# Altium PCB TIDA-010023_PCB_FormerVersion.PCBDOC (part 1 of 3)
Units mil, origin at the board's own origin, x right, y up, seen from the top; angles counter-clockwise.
Board outline 4724.44 x 3937.01 mil, 2 copper layers (Top Layer, Bottom Layer), stack 62 mil thick; 263 components, 126 nets, 611 pads, 186 vias.
Unrouted connection lines stored in the file: 58.
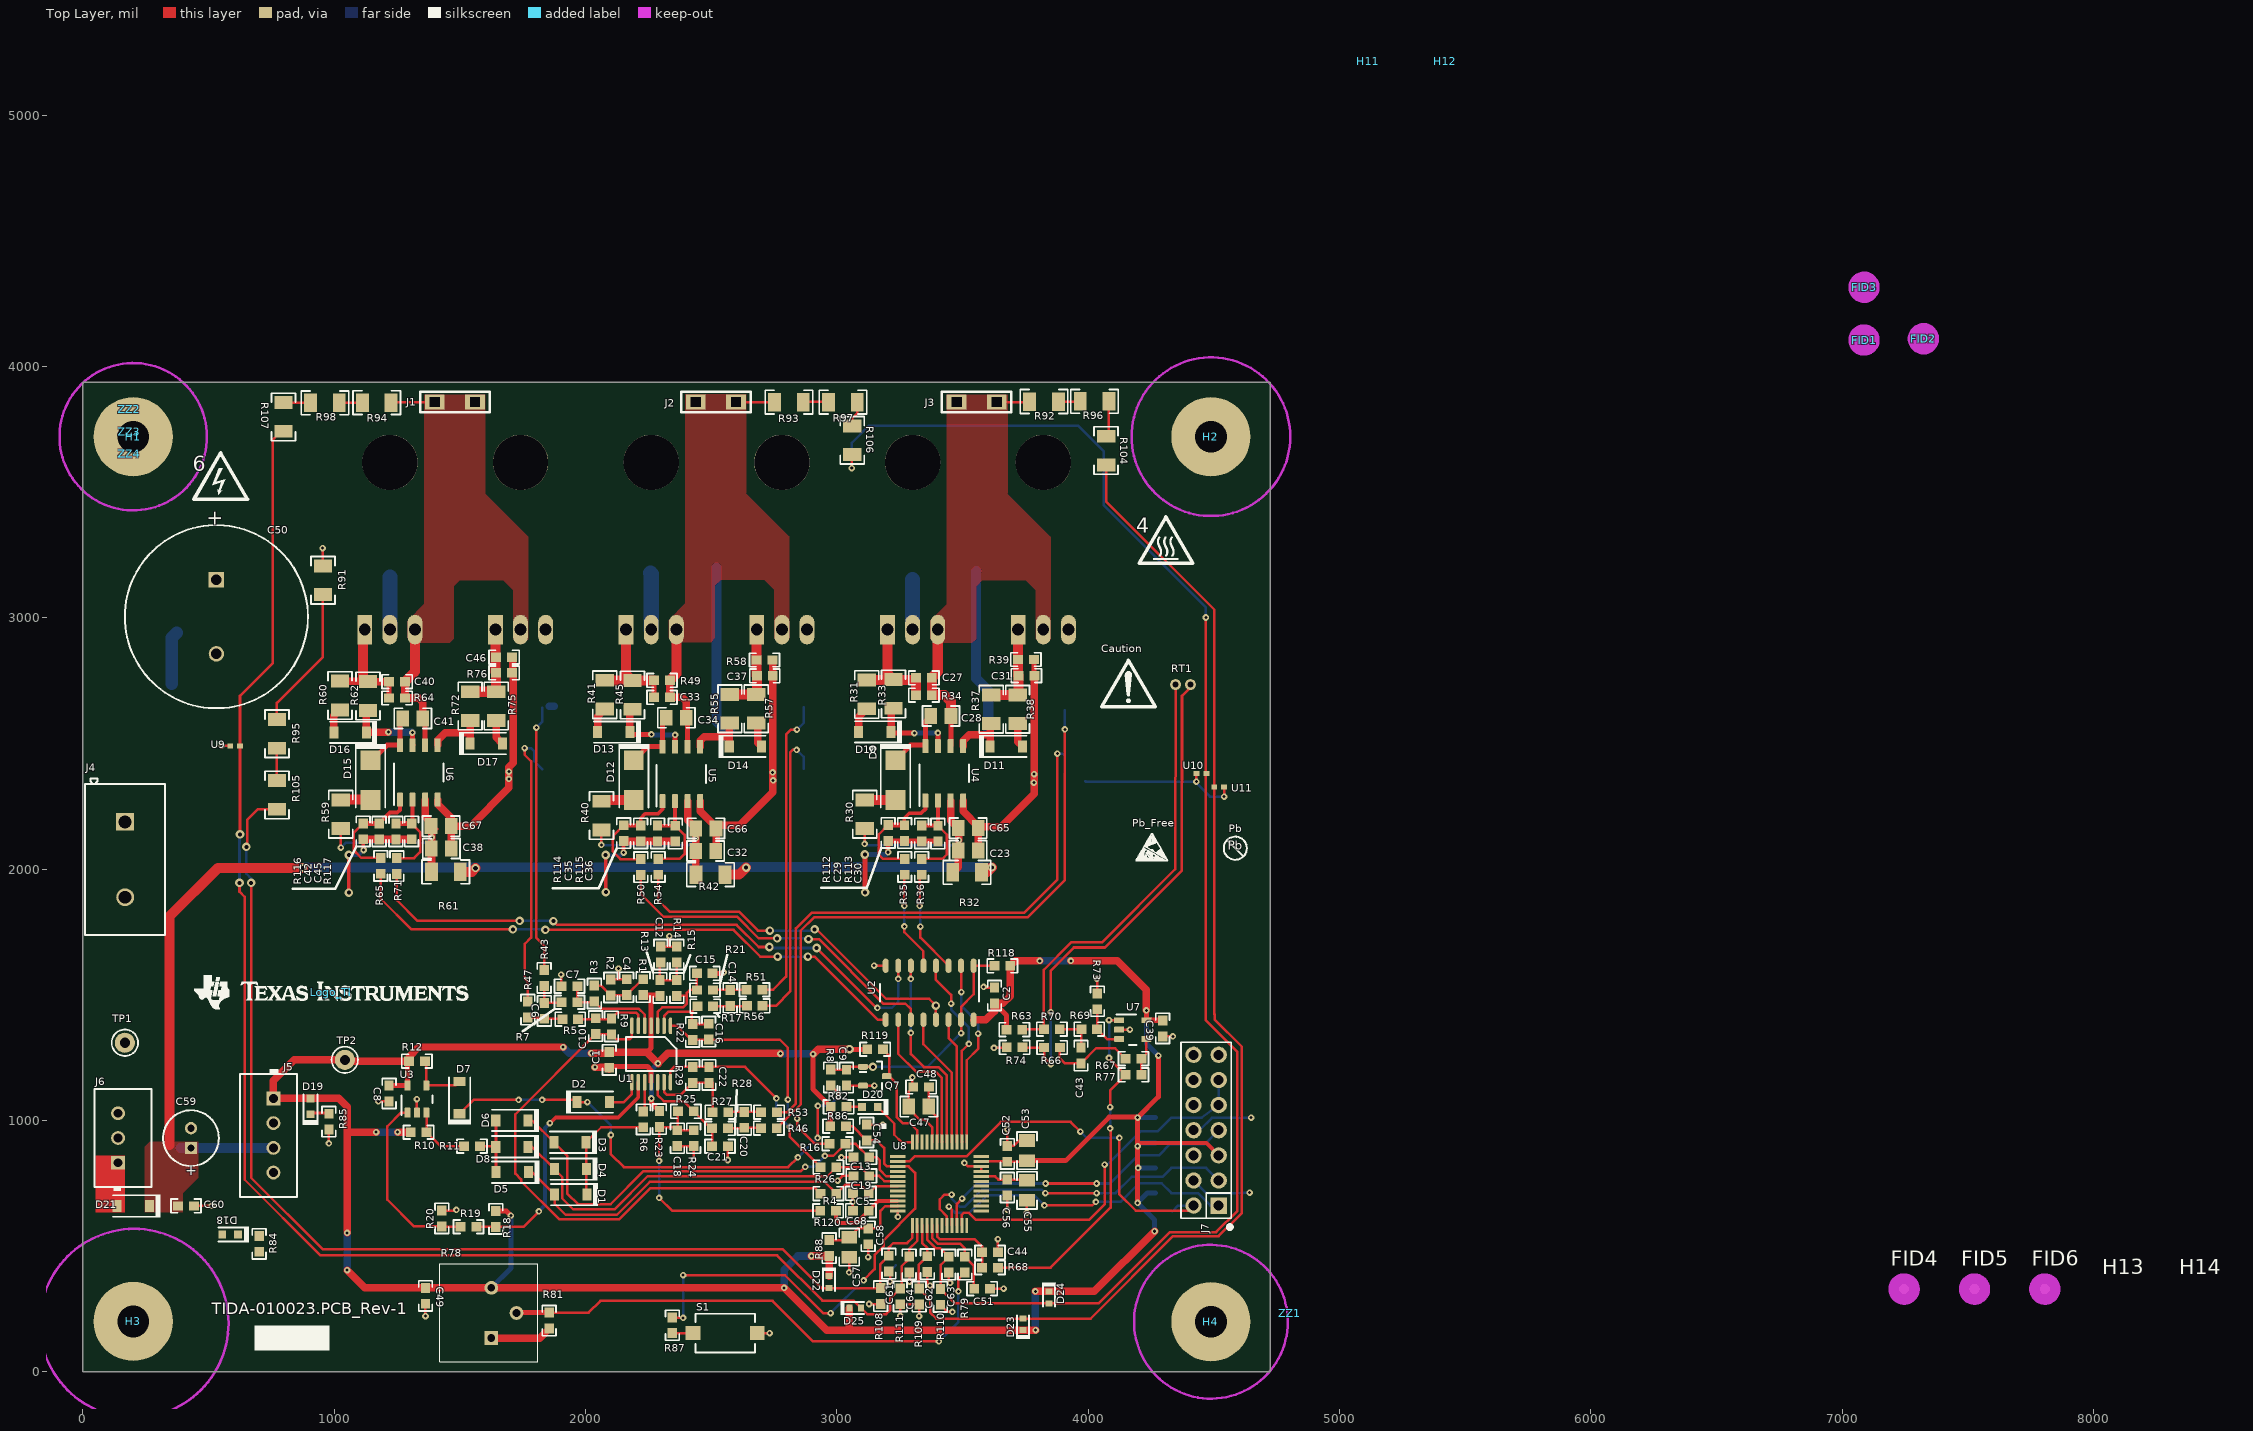
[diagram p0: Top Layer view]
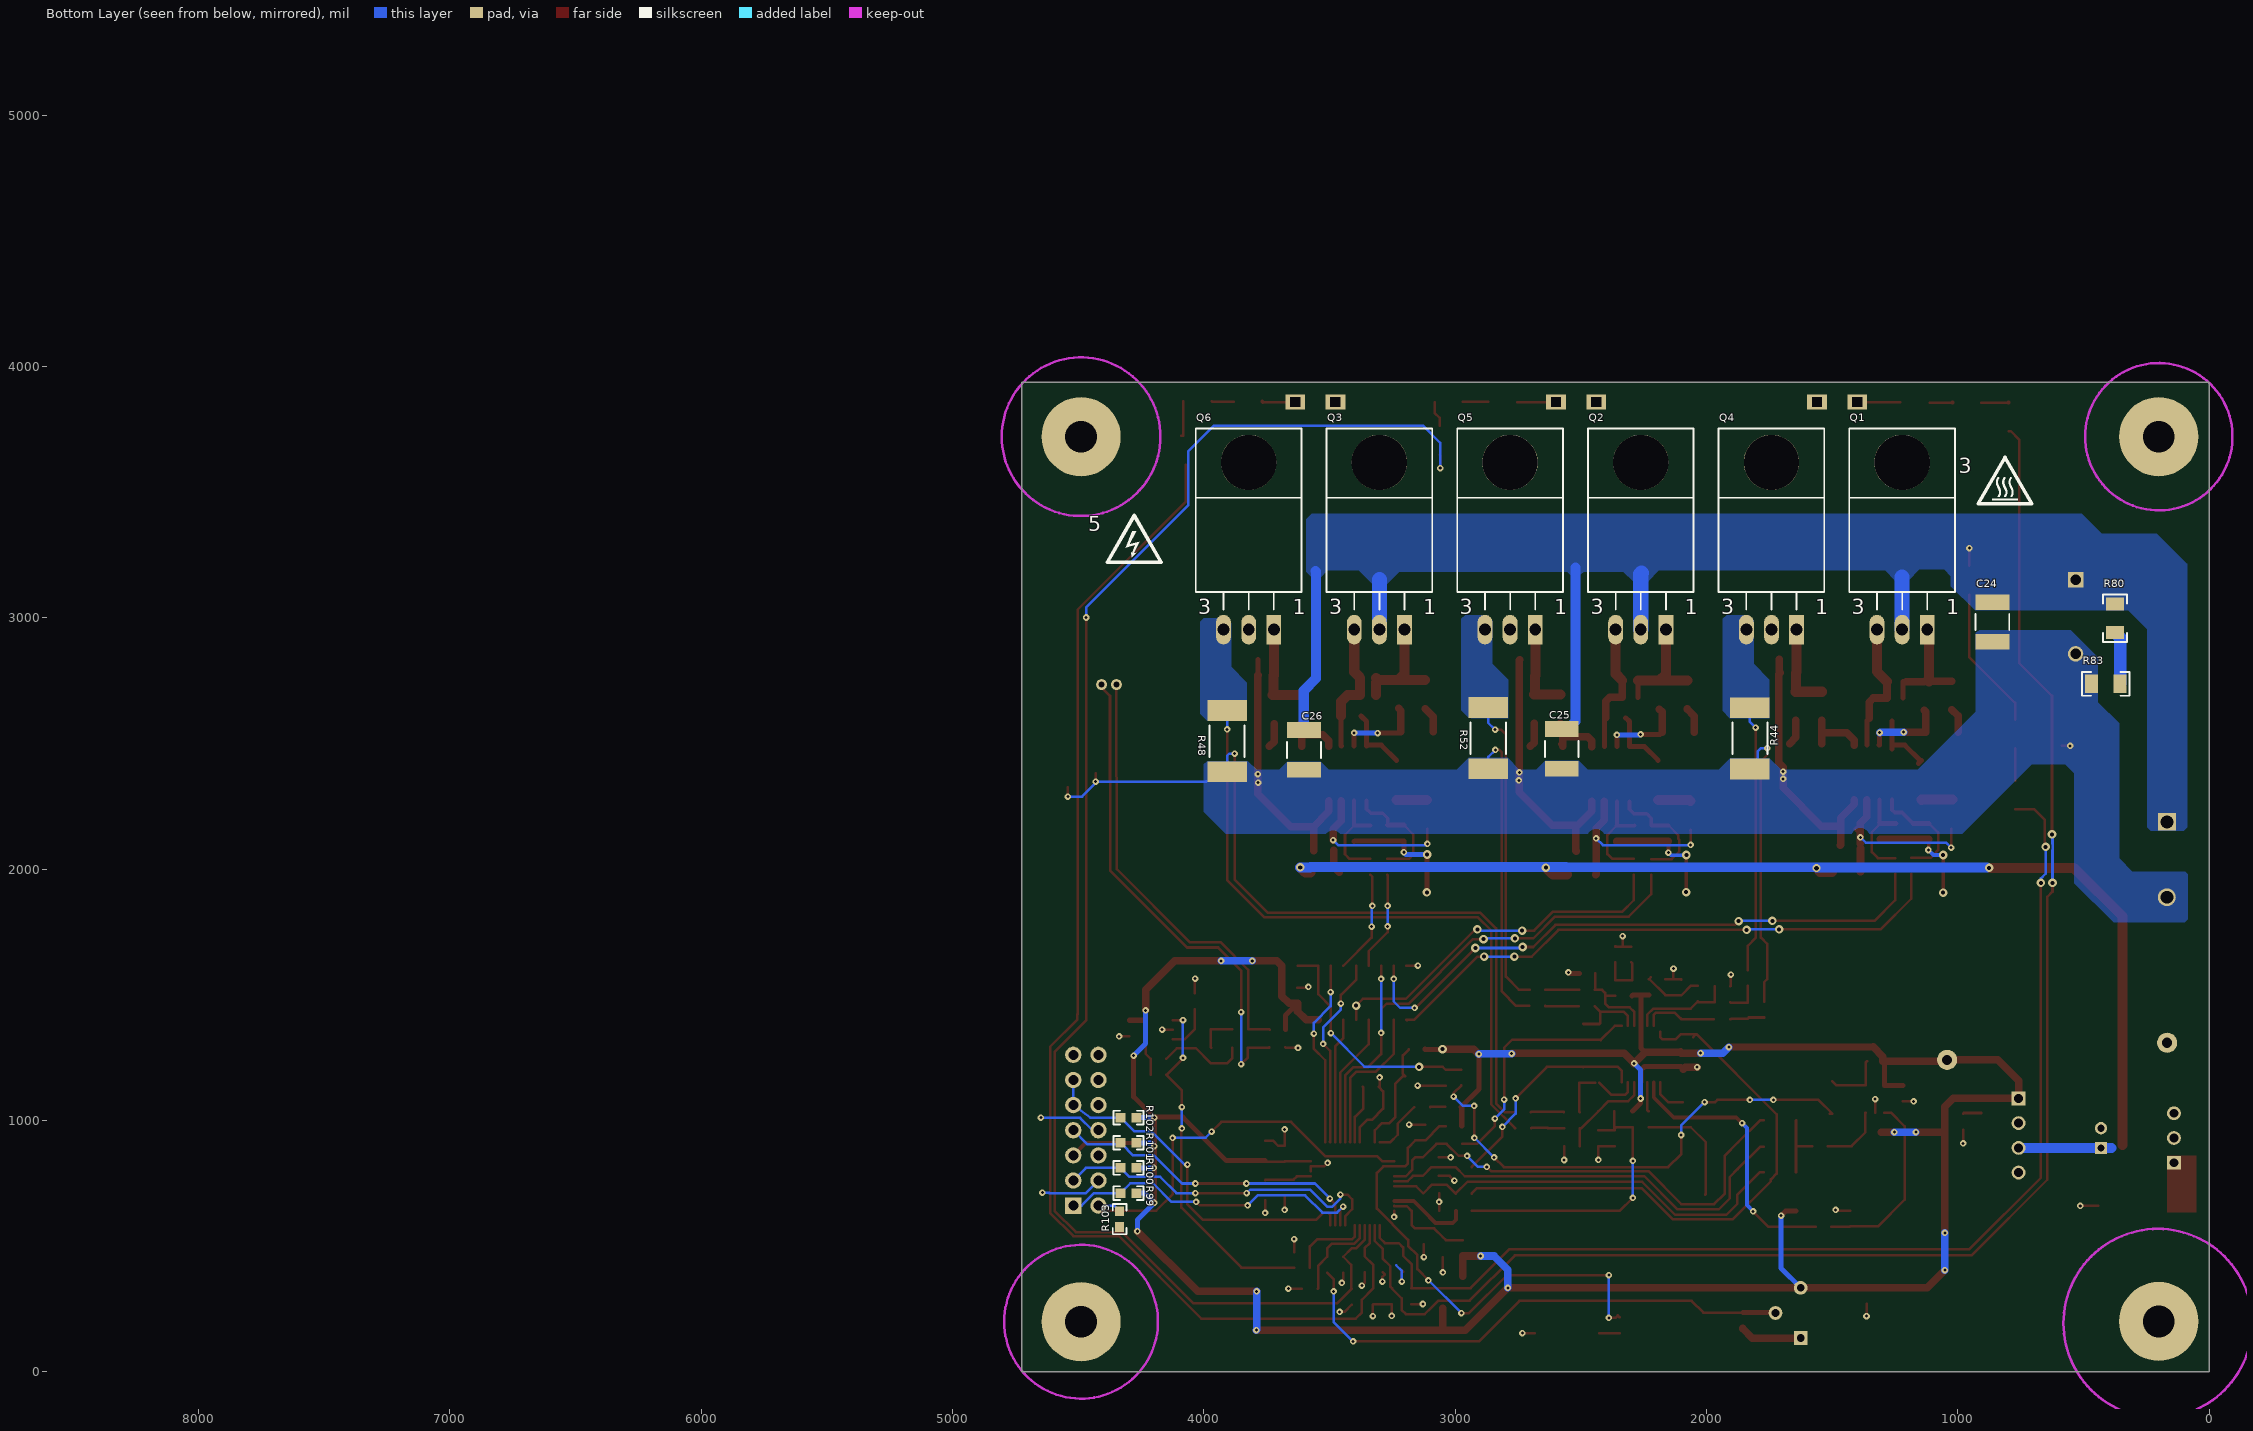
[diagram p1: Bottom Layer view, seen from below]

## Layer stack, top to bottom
Top Solder: solder mask 0.4, Solder Resist, Dk 3.5
Top Layer: signal copper 1.4
Dielectric1: core 59.2, FR-4, Dk 4.8
Bottom Layer: signal copper 1.4
Bottom Solder: solder mask 0.4, Solder Resist, Dk 3.5

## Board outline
0,0 0,3937.01 4723.44,3937.01 4724.44,0

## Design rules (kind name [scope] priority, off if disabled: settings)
AcuteAngle [All] p1: minimum=4.50000000000000E+0001 checktracksonly=FALSE
AssemblyTestPointUsage [All] p1: valid=2
BoardOutlineClearance BoardOutlineClearance_MountingHoles [OnCopper and InComponentClass('Mounting Holes')] p1: gap=40 ignorepadtopadclearanceinfootprint=FALSE
BoardOutlineClearance BoardOutlineClearance_Poly [OnCopper and IsPoly] p2: gap=25 ignorepadtopadclearanceinfootprint=FALSE
BoardOutlineClearance [OnCopper and Not InComponentClass('Logo') and not InComponentClass('FiducialMark') and not InRegion(1000,500,4000,800) and not InPoly] p3 off: gap=75 ignorepadtopadclearanceinfootprint=FALSE
Clearance Clearance_Keepouts [((IsTrack Or IsArc) And Not InPoly) And IsFree and IsKeepOut vs ((IsTrack Or IsArc) And Not InPoly) And IsFree and IsKeepOut] p1: gap=0 ignorepadtopadclearanceinfootprint=FALSE
Clearance Clearance_Poly [InPolygon] p2: gap=25 ignorepadtopadclearanceinfootprint=FALSE except(0: Arc-Hole Track-Hole SMDPad-Hole THPad-Hole Via-Hole Fill-Hole Poly-Hole Region-Hole Text-Hole)
Clearance Clearance_FiducialMark [IsKeepOut and InComponentClass('FiducialMark') vs IsPad and InComponentClass('FiducialMark')] p3: gap=0 ignorepadtopadclearanceinfootprint=FALSE
Clearance [All] p4: gap=6 ignorepadtopadclearanceinfootprint=FALSE
ComponentClearance ComponentClearance_MountingHoles_FiducialMarks [InComponentClass('Mounting Holes') vs InComponentClass('FiducialMark')] p1: gap=50 collisioncheckmode=3 verticalgap=10 showdistances=FALSE
ComponentClearance ComponentClearance_Shunt [InComponentClass('Header') vs InComponentClass('Shunt')] p2: gap=0 collisioncheckmode=3 verticalgap=0 showdistances=FALSE
ComponentClearance ComponentClearance_Logo [InComponentClass('Logo')] p3: gap=50 collisioncheckmode=3 verticalgap=10 showdistances=FALSE
ComponentClearance ComponentClearance_ScrewToNut [(HasFootprint('NY PMS 440 0025 PH')) vs (HasFootprint('Keystone_1902C'))] p4: gap=5 collisioncheckmode=3 verticalgap=5 showdistances=FALSE
ComponentClearance ComponentClearance_MountingHoles [InComponentClass('Mounting Holes')] p5: gap=-100 collisioncheckmode=3 verticalgap=0 showdistances=TRUE
ComponentClearance ComponentClearance_SmallPassives [HasFootprint('0201*') or HasFootprint('0402*') or HasFootprint('0508') or HasFootprint('0603*') or HasFootprint('0612') or HasFootprint('0805*') or HasFootprint('0815*') or HasFootprint('0830*') or HasFootprint('1206*') or HasFootprint('1210*') or HasFootprint('1808*') or HasFootprint('1812*') or HasFootprint('1825*') or HasFootprint('2010*') or HasFootprint('2220*') or HasFootprint('2225*') or HasFootprint('2512*') or HasFootprint('2728*') or HasFootprint('3518*') vs HasFootprint('0201*') or HasFootprint('0402*') or HasFootprint('0508') or HasFootprint('0603*') or HasFootprint('0612') or HasFootprint('0805*') or HasFootprint('0815*') or HasFootprint('0830*') or HasFootprint('1206*') or HasFootprint('1210*') or HasFootprint('1808*') or HasFootprint('1812*') or HasFootprint('1825*') or HasFootprint('2010*') or HasFootprint('2220*') or HasFootprint('2225*') or HasFootprint('2512*') or HasFootprint('2728*') or HasFootprint('3518*')] p6: gap=14.96 collisioncheckmode=3 verticalgap=10 showdistances=FALSE
ComponentClearance ComponentClearance_THtoSMT [IsThruComponent vs IsSMTComponent] p7: gap=0 collisioncheckmode=3 verticalgap=0 showdistances=FALSE
ComponentClearance ComponentClearance_THtoTH [IsThruComponent vs IsThruComponent] p8: gap=15 collisioncheckmode=3 verticalgap=30 showdistances=FALSE
ComponentClearance [All] p9: gap=30 collisioncheckmode=3 verticalgap=10 showdistances=FALSE
DiffPairsRouting [All] p1: maxlimit=100 minlimit=10 mostfreqgap=10 toplayer_minwidth=15 toplayer_maxwidth=15 toplayer_prefwidth=15 bottomlayer_minwidth=15 bottomlayer_maxwidth=15 bottomlayer_prefwidth=15 maxuncoupledlength=1000
FabricationTestPointUsage TestPointUsage [All] p1: valid=2 allowmultiple=FALSE
FabricationTestpoint Testpoint [All] p1: side=3 testpointundercomponent=TRUE minsize=40 maxsize=100 preferedsize=60 minholesize=0 maxholesize=40 preferedholesize=32 testpointgrid=1 allowsidetop=TRUE allowsidebottom=TRUE usegrid=TRUE gridtolerance=0.01
FanoutControl Fanout_LCC [IsLCC] p1: bgadir=Out bgaviamode=Centered fanoutstyle=Auto fanoutdirection=Alternating viagrid=1 // Fanout_LCC (Default Rule)
FanoutControl Fanout_BGA [IsBGA] p2: bgadir=Out bgaviamode=Centered fanoutstyle=Auto fanoutdirection=Alternating viagrid=1 // Fanout_BGA (Default Rule)
FanoutControl Fanout_Default [All] p4: bgadir=Out bgaviamode=Centered fanoutstyle=Auto fanoutdirection=Alternating viagrid=1 // Fanout_Default (Default Rule)
FanoutControl Fanout_Small [(CompPinCount < 5)] p5: bgadir=Out bgaviamode=Centered fanoutstyle=Auto fanoutdirection=OutThenIn viagrid=1 // Fanout_Small (Default Rule)
Height [All] p1: minheight=0 maxheight=5000 prefheight=500
HoleSize [All] p1: absolutevalues=TRUE maxlimit=251 minlimit=7.87 maxpercent=80.000 minpercent=20.000
MinimumAnnularRing MinimumAnnularRing_ThermalPadVias [IsVia and InAnyComponent] p1: minimumring=5.91
MinimumAnnularRing [All] p2: minimumring=8
MinimumSolderMaskSliver MinimumSolderMaskSliver_Logo [InComponentClass('Logo') vs InComponentClass('Logo')] p1: minsoldermaskwidth=0.7
MinimumSolderMaskSliver [All] p2: minsoldermaskwidth=3.94
PlaneConnect [All] p1: planeconnectstyle=Relief reliefexpansion=10 reliefentries=4 reliefconductorwidth=10 reliefairgap=10
PolygonConnect [All] p1: connectstyle=Direct reliefconductorwidth=10 reliefentries=4 polygonreliefangle="90 Angle" airgapwidth=10
RoutingVias ThermalPadVias [IsVia and InAnyComponent] p1: holewidth=7.87 width=19.68 viastyle="Through Hole" minholewidth=7.87 minwidth=19.68 maxholewidth=12.99 maxwidth=23.62
RoutingVias [All] p2: holewidth=16 width=34 viastyle="Through Hole" minholewidth=7.87 minwidth=26 maxholewidth=40 maxwidth=65
SilkToBoardRegionClearance [Not ((IsComment or IsDesignator) And (Hide <> 'False')) and not InRegion(1000,500,4000,800)] p1:
SilkToSilkClearance SilkToSilkClearance_Pb-FreeLogo [(HasFootprint('Pb-Free_Overlay_Medium') OR HasFootprint('Pb-Free_Overlay_Small')) vs (HasFootprint('Pb-Free_Overlay_Medium') OR HasFootprint('Pb-Free_Overlay_Small'))] p1: silktosilkclearance=0
SilkToSilkClearance [All] p2: silktosilkclearance=0
SilkToSolderMaskClearance SilkToComponentPadClearance [(IsPad or IsFill or IsRegion) and InAnycomponent] p1: minsilkscreentomaskgap=0 clearancetoexposedcopper=TRUE
SilkToSolderMaskClearance "Silk to Solder Mask Opening" [All] p2: minsilkscreentomaskgap=0 clearancetoexposedcopper=FALSE
SolderMaskExpansion [All] p1: expansion=1.97
Width [All] p1: maxlimit=300 minlimit=6 preferedwidth=10 minimp=50.000000 maximp=50.000000 favimp=50.000000 checkconnectedcopper=TRUE
14 further rules are at their usual default settings.

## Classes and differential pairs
component class TIDA-010023_MCU: C47 C48 C49 C50 C51 C52 C53 C54 C55 C56 C57 C58 C59 C60 C61 C62 C63 C64 C68 D18 D19 D20 D21 D22 D23 D24 D25 J4 J5 J6 J7 R78 R79 R80 R81 R82 R83 R84 R85 R86 R87 R88 R91 R92 R93 R94 R95 R96 R97 R98 R99 R100 R101 R102 R103 R104 R105 R106 R107 R108 R109 R110 R111 R120 S1 TP1 TP2 U8 U9 U10 U11
component class TIDA-010023_Inverter: C23 C24 C25 C26 C27 C28 C29 C30 C31 C32 C33 C34 C35 C36 C37 C38 C39 C40 C41 C42 C43 C44 C45 C46 C65 C66 C67 D9 D10 D11 D12 D13 D14 D15 D16 D17 J1 J2 J3 Q1 Q2 Q3 Q4 Q5 Q6 R30 R31 R32 R33 R34 R35 R36 R37 R38 R39 R40 R41 R42 R43 R44 R45 R46 R47 R48 R49 R50 R51 R52 R53 R54 R55 R56 R57 R58 R59 R60 R61 R62 R63 R64 R65 R66 R67 R68 R69 R70 R71 R72 R73 R74 R75 R76 R77 R112 R113 R114 R115 R116 R117 RT1 U4 U5 U6
component class TIDA-010023_Current_Sensing: C1 C2 C4 C5 C6 C7 C8 C9 C10 C12 C13 C14 C15 C16 C18 C19 C20 C21 C22 D1 D2 D3 D4 D5 D6 D7 D8 Q7 R1 R2 R3 R4 R5 R6 R7 R8 R9 R10 R11 R12 R13 R14 R15 R16 R17 R18 R19 R20 R21 R22 R23 R24 R25 R26 R27 R28 R29 R118 R119 U1 U2 U3
component class Header: J7
component class AssemblyNote: ZZ1 ZZ2 ZZ3 ZZ4
component class FiducialMark: FID1 FID2 FID3 FID4 FID5 FID6
component class TIDA-010023_EVM_Hardware: 3 4 5 6 Caution FID1 FID2 FID3 FID4 FID5 FID6 H1 H2 H3 H4 H11 H12 H13 H14 Logo_TI Pb Pb_Free ZZ1 ZZ2 ZZ3 ZZ4
component class "Mounting Holes": H1 H2 H3 H4
component class Logo: Logo_TI

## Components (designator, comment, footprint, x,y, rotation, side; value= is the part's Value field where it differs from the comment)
3 "CAUTION HOT SURFACE" IEC_HotSurface_small 812,3546 r180 bottom
4 "CAUTION HOT SURFACE" IEC_HotSurface_small 4309,3309 r0 top
5 "HIGH VOLTAGE" IEC_HighVoltage_small 4276.5,3309.5 r180 bottom
6 "HIGH VOLTAGE" IEC_HighVoltage_small 548,3559 r0 top
C1 "0603YC104JAT2A" 0603 2094,1241 r270 top value=0.1uF
C2 "0603YC104JAT2A" 0603 3627,1497 r270 top value=0.1uF
C4 "0603YC104JAT2A" 0603 2163,1530 r270 top value=0.1uF
C5 "06035A221FAT2A" 0603 3095,710 r180 top value=220pF
C6 "06035A221FAT2A" 0603 1836,1436 r90 top value=220pF
C7 "06035A221FAT2A" 0603 1936,1534 r180 top value=220pF
C8 "0603YC104JAT2A" 0603 1218,1107 r270 top value=0.1uF
C9 "06035A221FAT2A" 0603 3038,1170 r270 top value=220pF
C10 "06035A221FAT2A" 0603 2040,1375 r90 top value=22pF
C12 "0603YC104JAT2A" 0603 2299,1660 r90 top value=0.1uF
C13 "06035A221FAT2A" 0603 3097,853 r180 top value=220pF
C14 "06035A221FAT2A" 0603 2575,1487 r90 top value=220pF
C15 "06035A221FAT2A" 0603 2474,1585 r0 top value=220pF
C16 "06035A221FAT2A" 0603 2490,1353 r90 top value=22pF
C18 "0603YC104JAT2A" 0603 2364.98,929.2 r270 top value=0.1uF
C19 "06035A221FAT2A" 0603 3097,779 r180 top value=220pF
C20 "06035A221FAT2A" 0603 2631.98,1002.2 r90 top value=220pF
C21 "06035A221FAT2A" 0603 2534.98,897.2 r0 top value=220pF
C22 "06035A221FAT2A" 0603 2491,1181 r270 top value=22pF
C23 "C2012X5R1E106K125AB" 0805_HV 3522,2074 r180 top value=10uF
C24 "C1812V104KDRACTU" 1812_254 862,2983 r270 bottom value=0.1uF
C25 "C1812V104KDRACTU" 1812_254 2575,2478 r270 bottom value=0.1uF
C26 "C1812V104KDRACTU" 1812_254 3601,2474 r270 bottom value=0.1uF
C27 "GRM188R71E222KA01D" 0603 3346,2761 r0 top value=2200pF
C28 "C0805C105K3RACTU" 0805_HV 3414,2609 r0 top value=1uF
C29 "06035A221FAT2A" 0603 3269,2143 r270 top value=220pF
C30 "06035A221FAT2A" 0603 3402,2141 r270 top value=220pF
C31 "GRM188R71E222KA01D" 0603 3754,2770 r0 top value=2200pF
C32 "C2012X5R1E106K125AB" 0805_HV 2478,2072 r180 top value=10uF
C33 "GRM188R71E222KA01D" 0603 2304,2683 r0 top value=2200pF
C34 "C0805C105K3RACTU" 0805_HV 2361,2602 r0 top value=1uF
C35 "06035A221FAT2A" 0603 2219.3,2142 r270 top value=220pF
C36 "06035A221FAT2A" 0603 2357.3,2141 r270 top value=220pF
C37 "GRM188R71E222KA01D" 0603 2713,2769 r0 top value=2200pF
C38 "C2012X5R1E106K125AB" 0805_HV 1426,2082 r180 top value=10uF
C39 "0603YC104JAT2A" 0603 4296,1366 r270 top value=0.1uF
C40 "GRM188R71E222KA01D" 0603 1250,2745.7 r0 top value=2200pF
C41 "C0805C105K3RACTU" 0805_HV 1312.52,2599.6 r0 top value=1uF
C42 "06035A221FAT2A" 0603 1178.52,2149.6 r270 top value=220pF
C43 "0603YC104JAT2A" 0603 3971,1258 r270 top value=0.1uF
C44 "0603YC104JAT2A" 0603 3609,475 r180 top value=0.1uF
C45 "06035A221FAT2A" 0603 1245.52,2149.6 r270 top value=220pF
C46 "GRM188R71E222KA01D" 0603 1675.68,2843.5 r0 top value=2200pF
C47 "GRM21BR71C475KA73L" 0805_HV 3326,1055 r0 top value=4.7uF
C48 "0603YC104JAT2A" 0603 3335,1133 r0 top value=0.1uF
C49 "0603YC104JAT2A" 0603 1363,302 r90 top value=0.1uF
C50 "UCS2W680MHD" CS_1800x3150 531,3004 r270 top value=68uF
C51 "0603YC104JAT2A" 0603 3578,331 r180 top value=0.1uF
C52 "0603YC104JAT2A" 0603 3678,867 r90 top value=0.1uF
C53 "GRM21BR71C475KA73L" 0805_HV 3756,880 r90 top value=4.7uF
C54 "0603YC104JAT2A" 0603 3118,952 r90 top value=0.1uF
C55 "GRM21BR71C475KA73L" 0805_HV 3756,722 r270 top value=4.7uF
C56 "0603YC104JAT2A" 0603 3678,733 r270 top value=0.1uF
C57 "GRM21BR71C475KA73L" 0805_HV 3049,496 r270 top value=4.7uF
C58 "0603YC104JAT2A" 0603 3124,539 r270 top value=0.1uF
C59 "URZ1E220MDD1TD" RZ_500x900 430,929.61 r90 top value=22uF
C60 "06033C104KAT2A" 0603 410,659.61 r0 top value=0.1uF
C61 "06033C473JAT2A" 0603 3207,430 r270 top value=0.047uF
C62 "06033C473JAT2A" 0603 3360,428 r270 top value=0.047uF
C63 "06033C473JAT2A" 0603 3445,426 r270 top value=0.047uF
C64 "06033C473JAT2A" 0603 3287,427 r270 top value=0.047uF
C65 "C0805C105K3RACTU" 0805_HV 3522,2163 r180 top value=1uF
C66 "C0805C105K3RACTU" 0805_HV 2479,2162 r180 top value=1uF
C67 "C0805C105K3RACTU" 0805_HV 1425,2171 r180 top value=1uF
C68 "06035A221FAT2A" 0603 3095,641 r180 top value=220pF
Caution "CAUTION.  READ USER GUIDE BEFORE USE" IEC_Caution_small 4160,2738 r0 top
D1 "1N5363" sod-123 1941,705 r180 top value=30V
D2 "1N5363BRLG" sod-123 2030,1073 r0 top value=30V
D3 "US1M-13-F" sod-123 1938,913 r180 top value=30V
D4 "US1M-13-F" sod-123 1940,806 r180 top value=30V
D5 "1N5363" sod-123 1708,794 r180 top value=30V
D6 "1N5363BRLG" sod-123 1707,1000 r180 top value=30V
D7 "1N5363BRLG" sod-123 1499,1091 r90 top value=30V
D8 "1N5363BRLG" sod-123 1707,895 r180 top value=30V
D9 "US1M-13-F" SMA 3233,2354 r270 top value=1000V
D10 "1N5819HW-7-F" SOD-123 3151,2546 r180 top value=40V
D11 "1N5819HW-7-F" SOD-123 3674,2488 r0 top value=40V
D12 "US1M-13-F" SMA 2192,2354 r270 top value=1000V
D13 "1N5819HW-7-F" SOD-123 2112,2545 r180 top value=40V
D14 "1N5819HW-7-F" SOD-123 2636,2488 r0 top value=40V
D15 "US1M-13-F" SMA 1144,2354 r270 top value=1000V
D16 "1N5819HW-7-F" SOD-123 1063,2544 r180 top value=40V
D17 "1N5819HW-7-F" SOD-123 1604.68,2499.5 r0 top value=40V
D18 "150060GS75000" WL-SMCW_GREEN 586,546 r180 top value=GREEN
D19 "150060GS75000" WL-SMCW_GREEN 905,1056 r90 top value=YELLOW
D20 "150060GS75000" WL-SMCW_GREEN 3131,1053 r180 top value=RED
D21 "1N5819HW-7-F" SOD-123 200,659.61 r180 top value=40V
D22 "CDBP0130L-G" SOD-723 2969,356.62 r270 top value=30V
D23 "CDBP0130L-G" SOD-723 3741,189 r90 top value=30V
D24 "CDBP0130L-G" SOD-723 3844,296 r270 top value=30V
D25 "CDBP0130L-G" SOD-723 3073,253 r0 top value=30V
FID1 "Fiducial" Fiducial10-30 7086.61,4105 r0 top
FID2 "Fiducial" Fiducial10-30 7322.83,4110 r0 top
FID3 "Fiducial" Fiducial10-30 7086.61,4315 r0 top
FID4 "Fiducial" Fiducial10-30 7246,329 r90 top
FID5 "Fiducial" Fiducial10-30 7526,329 r90 top
FID6 "Fiducial" Fiducial10-30 7806,329 r90 top
H1 "NY PMS 440 0025 PH" "NY PMS 440 0025 PH"#1 200,3730 r0 top locked
H2 "NY PMS 440 0025 PH" "NY PMS 440 0025 PH"#2 4488.19,3742 r0 top locked
H3 "NY PMS 440 0025 PH" "NY PMS 440 0025 PH"#3 200,200 r0 top locked
H4 "NY PMS 440 0025 PH" "NY PMS 440 0025 PH"#3 4488.19,199 r0 top locked
H11 "1902C" Keystone_1902C 5114,5215 r90 top
H12 "1902C" Keystone_1902C 5421,5215 r90 top
H13 "1902C" Keystone_1902C 8152,210 r90 top
H14 "1902C" Keystone_1902C 8459,210 r90 top
J1 "B2P-VH(LF)(SN)" "6.3mm 2P PHASE" 1560,3858.27 r180 top locked
J2 "B2P-VH(LF)(SN)" "6.3mm 2P PHASE" 2598.43,3858.27 r180 top locked
J3 "B2P-VH(LF)(SN)" "6.3mm 2P PHASE" 3636,3858.27 r180 top locked
J4 "OSTVI024152" Phoenix_1707027 168,2038 r270 top
J5 "B4B-XH-A(LF)(SN)" JST_B4B-XH-A 758,940 r270 top
J6 "0353120360" JST_B3B-XH-A 140,930 r90 top
J7 "PEC07DAAN" CONN_PEC07DAAN 4469,961 r90 top
Logo_TI "Texas Instruments" TI_Horizontal_Overlay_Small 987,1510 r0 top
Pb "Pb-Free Symbol" Pb-Free_Overlay_Small 4585,2083 r0 top
Pb_Free "ESD Susceptible" ESD_Overlay_small 4252,2082 r0 top
Q1 "IGBT" TO-220AB_HORIZONTAL 1221.18,2952.76 r180 bottom locked value="650 V"
Q2 "IGBT" TO-220AB_HORIZONTAL 2261.18,2952.76 r180 bottom locked value="650 V"
Q3 "IGBT" TO-220AB_HORIZONTAL 3301.18,2952.76 r180 bottom locked value="650 V"
Q4 "IGBT" TO-220AB_HORIZONTAL 1741.18,2952.76 r180 bottom locked value="650 V"
Q5 "IGBT" TO-220AB_HORIZONTAL 2781.18,2952.76 r180 bottom locked value="650 V"
Q6 "IGBT" TO-220AB_HORIZONTAL 3821.18,2952.76 r180 bottom locked value="650 V"
Q7 "MMBT2222A" SOT-23 3151,1176 r0 top value="40 V"
R1 "RT0603BRD074K99L" 0603 2228.98,1530.2 r270 top value=4.99k
R2 "RT0603BRD074K99L" 0603 2100,1529 r270 top value=4.99k
R3 "RT0603BRD074K99L" 0603 2035,1505 r270 top value=4.99k
R4 "CRCW0603100RFKEA" 0603 2966,709 r0 top value=100
R5 "CRCW06039K09FKEA" 0603 1939,1403 r0 top value=100
R6 "CRCW060310K0FKEA" 0603 2229.98,1004.2 r270 top value=10.0k
R7 "CRCW060331K6FKEA" 0603 1936,1470 r0 top value=100
R8 "CRCW0603100RFKEA" 0603 2975,1171 r90 top value=100
R9 "RT0603BRD074K99L" 0603 2103,1374 r270 top value=4.99k
R10 "CRCW060310K0FKEA" 0603 1336,953 r0 top value=10.0k
R11 "CRCW060310K0FKEA" 0603 1548,898 r0 top value=10.0k
R12 "CRCW060310K0FKEA" 0603 1329,1236 r180 top value=10.0k
R13 "RT0603BRD074K99L" 0603 2295.98,1527.2 r270 top value=4.99k
R14 "RT0603BRD074K99L" 0603 2363,1660 r270 top value=4.99k
R15 "RT0603BRD074K99L" 0603 2363,1527 r270 top value=4.99k
R16 "CRCW0603100RFKEA" 0603 3002,907 r0 top value=100
R17 "CRCW06039K09FKEA" 0603 2476,1455 r180 top value=100
R18 "CRCW060310K0FKEA" 0603 1643,608 r90 top value=10.0k
R19 "CRCW060321K5FKEA" 0603 1534,577 r0 top value=21.5k
R20 "CRCW06031M00FKEA" 0603 1428,610 r270 top value=21.5k
R21 "CRCW060331K6FKEA" 0603 2475,1519 r180 top value=100
R22 "RT0603BRD074K99L" 0603 2426,1352 r270 top value=4.99k
R23 "RT0603BRD074K99L" 0603 2293.98,1005.2 r90 top value=4.99k
R24 "RT0603BRD074K99L" 0603 2429.98,929.2 r90 top value=4.99k
R25 "RT0603BRD074K99L" 0603 2398.98,1036.2 r0 top value=4.99k
R26 "CRCW0603100RFKEA" 0603 2966,814 r0 top value=100
R27 "CRCW06039K09FKEA" 0603 2535.98,1033.2 r180 top value=100
R28 "CRCW060331K6FKEA" 0603 2534.98,968.2 r180 top value=100
R29 "RT0603BRD074K99L" 0603 2426,1181 r90 top value=4.99k
R30 "CRCW12063R30JNEA" 1206 3111,2218 r90 top value=3.3
R31 "RC1206FR-0712RL" 1206 3119,2695 r90 top value=12.0
R32 "RC0603FR-075R11L" 1206 3518,1987 r0 top value=5.11
R33 "CRCW12066R04FKEA" 1206 3225,2697 r90 top value=6.04
R34 "CRCW060320K0FKEA" 0603 3346,2692 r180 top value=20.0k
R35 "CRCW060351R1FKEA" 0603 3270,2009 r90 top value=51.1
R36 "CRCW060351R1FKEA" 0603 3337,2009 r90 top value=51.1
R37 "CRCW12066R04FKEA" 1206 3614,2636 r90 top value=6.04
R38 "RC1206FR-0712RL" 1206 3719,2636 r90 top value=12.0
R39 "CRCW060320K0FKEA" 0603 3752,2834 r180 top value=20.0k
R40 "CRCW12063R30JNEA" 1206 2063,2213 r90 top value=3.3
R41 "RC1206FR-0712RL" 1206 2076,2694 r90 top value=12.0
R42 "RC0603FR-075R11L" 1206 2497,1978 r0 top value=5.11
R43 "CRCW06030000Z0EA" 0603 1835,1567 r270 top value=0
R44 "CRE2512-FZ-R005E-3" CRE2512-R5_R9 1827,2520 r270 bottom value=0.005
R45 "CRCW12066R04FKEA" 1206 2187,2693 r90 top value=6.04
R46 "CRCW06030000Z0EA" 0603 2729,969 r0 top value=0
R47 "CRCW06030000Z0EA" 0603 1770,1441 r270 top value=0
R48 "CRE2512-FZ-R005E-3" CRE2512-R5_R9 3907,2509 r270 bottom value=0.005
R49 "CRCW060320K0FKEA" 0603 2304,2751 r180 top value=20.0k
R50 "CRCW060351R1FKEA" 0603 2220,2008 r90 top value=51.1
R51 "CRCW06030000Z0EA" 0603 2672,1520 r180 top value=0
R52 "CRE2512-FZ-R005E-3" CRE2512-R5_R9 2868,2521 r270 bottom value=0.005
R53 "CRCW06030000Z0EA" 0603 2730,1033 r0 top value=0
R54 "CRCW060351R1FKEA" 0603 2289,2009 r90 top value=51.1
R55 "CRCW12066R04FKEA" 1206 2574,2638 r90 top value=6.04
R56 "CRCW06030000Z0EA" 0603 2673,1456 r180 top value=0
R57 "RC1206FR-0712RL" 1206 2679,2638 r90 top value=12.0
R58 "CRCW060320K0FKEA" 0603 2712,2832 r180 top value=20.0k
R59 "CRCW12063R30JNEA" 1206 1026,2218 r90 top value=3.3
R60 "RC1206FR-0712RL" 1206 1023,2690.69 r90 top value=12.0
R61 "RC0603FR-075R11L" 1206 1444,1989 r0 top value=5.11
R62 "CRCW12066R04FKEA" 1206 1134,2688.69 r90 top value=6.04
R63 "CRCW060310K0FKEA" 0603 3706,1361 r0 top value=10.0k
R64 "CRCW060320K0FKEA" 0603 1250,2680.7 r180 top value=20.0k
R65 "CRCW060351R1FKEA" 0603 1185,2013 r90 top value=51.1
R66 "CRCW0603100RFKEA" 0603 3856,1290 r0 top value=100
R67 "CRCW06031K00FKEA" 0603 4180,1245.5 r0 top value=1.00k
R68 "CRCW0603100RFKEA" 0603 3609,414 r180 top value=100
R69 "CRCW06031K00FKEA" 0603 4004,1363.5 r0 top value=1.00k
R70 "CRCW0603100RFKEA" 0603 3855,1363 r0 top value=100
R71 "CRCW060351R1FKEA" 0603 1249,2012 r90 top value=51.1
R72 "CRCW12066R04FKEA" 1206 1540.68,2648.5 r90 top value=6.04
R73 "CRCW06031K00FKEA" 0603 4036,1474 r90 top value=1.00k
R74 "CRCW0603100RFKEA" 0603 3707,1291 r180 top value=100
R75 "RC1206FR-0712RL" 1206 1644.68,2648.5 r90 top value=12.0
R76 "CRCW060320K0FKEA" 0603 1675.68,2780.5 r180 top value=20.0k
R77 "CRCW06031K00FKEA" 0603 4180,1181 r180 top value=1.00k
R78 "3386P-1-203LF" BOURNS_3386P 1615,234 r90 top value=20k
R79 "CRCW0603100RFKEA" 0603 3509,426 r90 top value=100
R80 "CRCW1206300KJNEA" 1206 374,2998 r90 bottom value=300k
R81 "CRCW06031M00FKEA" 0603 1855,203.61 r90 top value=1.00Meg
R82 "CRCW06031K00FKEA" 0603 3007,1054 r180 top value=1.00k
R83 "CRCW1206300KJNEA" 1206 411,2737 r180 bottom value=300k
R84 "CR0603-FX-4991ELF" 0603 701,509 r90 top value=4.99k
R85 "CRCW06031K00FKEA" 0603 979,995 r90 top value=1.00k
R86 "CRCW06034K70JNEA" 0603 3005,977 r180 top value=4.7k
R87 "CRCW0603100RFKEA" 0603 2345,185 r90 top value=100
R88 "CRCW06030000Z0EA" 0603 2969,492 r270 top value=0
R91 "RC1206FR-07374KL" 1206 955,3149 r90 top value=374k
R92 "RC1206FR-07374KL" 1206 3824,3860 r180 top value=374k
R93 "RC1206FR-07374KL" 1206 2809,3858 r180 top value=374k
R94 "RC1206FR-07374KL" 1206 1169,3856 r0 top value=374k
R95 "RC1206FR-07374KL" 1206 772,2538 r90 top value=374k
R96 "RC1206FR-07374KL" 1206 4025,3861 r180 top value=374k
R97 "RC1206FR-07374KL" 1206 3024,3858 r180 top value=374k
R98 "RC1206FR-07374KL" 1206 963,3855 r0 top value=374k
R99 "CRCW06034K70JNEA" 0603 4299.39,711 r180 bottom value=4.7k
R100 "CRCW06034K70JNEA" 0603 4299.39,811 r180 bottom value=4.7k
R101 "CRCW06034K70JNEA" 0603 4299.39,911 r180 bottom value=4.7k
R102 "CRCW06034K70JNEA" 0603 4299.39,1011 r180 bottom value=4.7k
R103 "CRCW06034K70JNEA" 0603 4335,607 r270 bottom value=4.7k
R104 "RC1206FR-07374KL" 1206 4071,3665 r90 top value=374k
R105 "RC1206FR-07374KL" 1206 772,2295 r90 top value=374k
R106 "RC1206FR-07374KL" 1206 3061,3706 r90 top value=374k
R107 "RC1206FR-07374KL" 1206 798,3799 r90 top value=374k
R108 "CRCW06039K09FKEA" 0603 3174,301 r90 top value=9.09k
R109 "CRCW06039K09FKEA" 0603 3327,299 r90 top value=9.09k
R110 "CRCW06039K09FKEA" 0603 3412,298 r90 top value=9.09k
R111 "CRCW06039K09FKEA" 0603 3252,300 r90 top value=9.09k
R112 "CRCW060351R1FKEA" 0603 3204,2144 r270 top value=51.1
R113 "CRCW060351R1FKEA" 0603 3337,2142 r270 top value=51.1
R114 "CRCW060351R1FKEA" 0603 2151.3,2143 r270 top value=51.1
R115 "CRCW060351R1FKEA" 0603 2286.3,2142 r270 top value=51.1
R116 "CRCW060351R1FKEA" 0603 1115,2150 r270 top value=51.1
R117 "CRCW060351R1FKEA" 0603 1308,2150 r270 top value=51.1
R118 "CRCW060310K0FKEA" 0603 3658,1615 r180 top value=10.0k
R119 "CRCW060310K0FKEA" 0603 3152,1283 r0 top value=10.0k
R120 "CRCW0603100RFKEA" 0603 2965,640 r0 top value=100
RT1 "MF52-103" NTCALUG03 4377,2734 r90 top value="10k ohm"
S1 "434121025816" SW_434121025816 2555,154 r0 top
TP1 "5000" Keystone5000 167,1309 r0 top
TP2 "5000" Keystone5000 1042,1241 r90 top
U1 "TLV9064" tssop-14 2260.98,1264.2 r270 top
U2 "SN74AHC367DR" D0016A_N 3369,1508 r270 top
U3 "TLV1701AIDBVR" DBV0005A_N 1329,1085 r90 top
U4 "UCC27712DR" D0008B_HV 3427,2381 r90 top
U5 "UCC27712DR" D0008B_HV 2381,2378.6 r90 top
U6 "UCC27712DR" D0008B_HV 1336.52,2384.6 r90 top
U7 "TLV9001IDBV" DBV0005A_N 4177,1361.19 r0 top
U8 "TMS320F28027F" PT-48 3408,748 r270 top value=TMS320F2802xPTA
U9 "TPD1E10B06DPYR" DPY0002A 606,2490 r180 top
U10 "TPD1E10B06DPYR" DPY0002A 4450,2381 r180 top
U11 "TPD1E10B06DPYR" DPY0002A 4521,2326 r0 top
ZZ1 "This Assembly Note is for PCB labels only" AssemblyNoteLabel 4802,233 r90 top
ZZ2 "These assemblies are ESD sensitive, ESD precautions shall be observed." AssemblyNote 185,3829.11 r0 top
ZZ3 "These assemblies must be clean and free from flux and all contaminants. Use of no clean flux is not acceptable." AssemblyNote 185,3740.56 r0 top
ZZ4 "These assemblies must comply with workmanship standards IPC-A-610 Class 2, unless otherwise specified." AssemblyNote 185,3652 r0 top

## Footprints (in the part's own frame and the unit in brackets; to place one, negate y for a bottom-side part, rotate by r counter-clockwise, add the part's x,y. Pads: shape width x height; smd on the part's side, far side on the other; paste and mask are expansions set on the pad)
"6.3mm 2P PHASE" [mm]
  rect 2x1.5 hole 1 square: 1(0,0) 2(4.06,0)
  silkscreen extent -1.47,-1.02 5.54,1.02
0603 [mm] "0603 from SM-752 data"
  rect 1x0.95 smd: 1(-0.8,0) 2(0.8,0)
  silkscreen extent -1.52,-0.69 1.52,0.69, body extent -0.87,-0.47 0.87,0.47, height 1
0805_HV [mil] "0805 with 30mil clearance between pads"
  rect 50x63 smd: 1(-40,0) 2(40,0)
  silkscreen extent -74,-40 74,40, body extent -43,-29 43,29, height 57
1206 [mm] "1206 from SM-752 data"
  rect 1.3x1.85 smd: 1(-1.45,0) 2(1.45,0)
  silkscreen extent -2.4,-1.21 2.4,1.21, body extent -1.7,-0.9 1.7,0.9, height 1.35
1812_254 [mm] "SMD, 2-Leads, Body 4.8x3.4mm"
  rect 1.6x3.4 smd: 1(-2,0) 2(2,0)
  silkscreen extent -0.8,-1.7 0.8,1.7, body extent -2.4,-1.7 2.4,1.7, height 2.54
AssemblyNote [mil] "Assembly Note"
AssemblyNoteLabel [mil] "Assembly Note for PCB Labels"
BOURNS_3386P [mil] "BOURND"
  rect 55x55 hole 31: 1(-100,-10)
  round 55 hole 31: 2(0,-110) 3(100,-10)
  silkscreen extent -195,-195 195,195, body extent -193,-192 193,193, height 201
CONN_PEC07DAAN [mm] "SULLINS"
  rect 1.65x1.65 hole 1.016 mask+0: 1(-7.62,-1.27)
  round 1.65 hole 1.016 mask+0: 2(-7.62,1.27) 3(-5.08,-1.27) 4(-5.08,1.27) 5(-2.54,-1.27) 6(-2.54,1.27) 7(0,-1.27) 8(0,1.27) 9(2.54,-1.27) 10(2.54,1.27) 11(5.08,-1.27) 12(5.08,1.27) 13(7.62,-1.27) 14(7.62,1.27)
  silkscreen extent -9.99,-2.6 8.89,2.54, body extent -8.95,-2.6 8.95,2.6, height 8.38
CRE2512-R5_R9 [mm] "SMD, 2-Leads, Body 6.45x3.35mm, Pitch 6.2mm"
  rect 2.1x4 smd: 1(-3.1,0) 2(3.1,0)
  silkscreen extent -1.6,-1.78 1.6,1.78, body extent -3.32,-1.77 3.32,1.77, height 0.9
CS_1800x3150 [mm] "TH, 2-Leads, Body 18x31.5mm, Pin Spacing 7.5mm"
  rect 1.55x1.55 hole 1.05: 1(-3.75,0)
  round 1.55 hole 1.05: 2(3.75,0)
  silkscreen extent -9.25,-9.25 9.25,9.25, body extent -9.25,-9.26 9.25,9.26, height 33.5
D0008B_HV [mm] "SOIC, 8-Leads, Body 4.9x3.9mm, Pitch 1.27mm, HV / Isolation option"
  rrect17% 1.4x0.6 smd: 1(-2.75,1.905) 2(-2.75,0.635) 3(-2.75,-0.635) 4(-2.75,-1.905) 5(2.75,-1.905) 6(2.75,-0.635) 7(2.75,0.635) 8(2.75,1.905)
  silkscreen extent -3.3,-2.5 0.9,2.5, body extent -3,-2.45 3,2.45, height 1.63
D0016A_N [mm] "SOIC, 16-Leads, Body 9.9x3.9mm, Pitch 1.27mm, IPC Medium Density"
  oval 1.45x0.6 smd: 1(-2.725,4.445) 2(-2.725,3.175) 3(-2.725,1.905) 4(-2.725,0.635) 5(-2.725,-0.635) 6(-2.725,-1.905) 7(-2.725,-3.175) 8(-2.725,-4.445) 9(2.725,-4.445) 10(2.725,-3.175) 11(2.725,-1.905) 12(2.725,-0.635) 13(2.725,0.635) 14(2.725,1.905) 15(2.725,3.175) 16(2.725,4.445)
  silkscreen extent -3.3,-5 0.9,5, body extent -3,-4.95 3,4.95, height 1.6
DBV0005A_N [mm] "SOT23, 5-Leads, Body 2.9x1.6mm, Pitch 0.95mm, Lead Span 2.8mm, IPC Medium Density"
  rrect17% 1x0.6 smd: 1(-1.375,0.95) 2(-1.375,0) 3(-1.375,-0.95) 4(1.375,-0.95) 5(1.375,0.95)
  silkscreen extent -1.63,-1.55 0.38,1.55, body extent -1.42,-1.46 1.42,1.46, height 1.09
DPY0002A [mm] "R-PX2SON-N2"
  rect 0.6x0.5 smd: 1(-0.5,0) 2(0.5,0)
  body extent -0.55,-0.35 0.55,0.35, height 0.4
ESD_Overlay_small [mil]
  silkscreen extent -62,-48 64,61
Fiducial10-30 [mm]
  round 1 smd mask+1: 1(0,0)
  Top Layer keep-out circle w1.678: c0,0 r0.75
IEC_Caution_small [mil]
  silkscreen extent -107,-93 107,92
IEC_HighVoltage_small [mil]
  silkscreen extent -107,-88 107,97
IEC_HotSurface_small [mil]
  silkscreen extent -107,-93 107,92
JST_B3B-XH-A [mm] "Header (Shrouded), 2.5mm, 3x1, TH"
  rect 1.4x1.4 hole 0.9: 1(-2.5,0)
  round 1.4 hole 0.9: 2(0,0) 3(2.5,0)
  Top Layer lines w0.1: -0.32,0.32 0,0 ; 0.32,0.32 0,0 ; -0.32,-0.32 0,0 ; 0.32,-0.32 0,0
  silkscreen extent -5.35,-3.37 4.95,2.38, body extent -4.95,-3.37 4.95,2.38, height 7
JST_B4B-XH-A [mm] "Header (Shrouded), 2.5mm, 4x1, TH"
  rect 1.4x1.4 hole 0.9: 1(-3.75,0)
  round 1.4 hole 0.9: 2(-1.25,0) 3(1.25,0) 4(3.75,0)
  silkscreen extent -6.7,-3.37 6.2,2.38, body extent -6.2,-3.37 6.2,2.38, height 7
Keystone5000 [mil] "For Keystone 500x miniature loop terminals"
  round 80 hole 40: 1(0,0)
  silkscreen extent -52,-52 52,52, body extent -49,-49 49,49, height 182
Keystone_1902C [mil]
  round 1 on Mech3: 0(0,0)
  body extent -145,-126 146,126, height 501
NTCALUG03 [mm] "NTC Thermistor, Mini Lug Sensor, Pitch 1.5mm"
  round 1.1 hole 0.6: 1(0,0.75) 2(0,-0.75)
"NY PMS 440 0025 PH"#1 [mm] "4-40 nylon screw and mounting hole"
  round 8 hole 3.2: 1(0,-0.242)
  body extent -3.3,-3.3 3.3,3.3, height 2.69
"NY PMS 440 0025 PH"#2 [mm] "4-40 nylon screw and mounting hole"
  round 8 hole 3.2: 1(0,-0.547)
  body extent -3.3,-3.3 3.3,3.3, height 2.69
"NY PMS 440 0025 PH"#3 [mm] "4-40 nylon screw and mounting hole"
  round 8 hole 3.2: 1(0,0)
  body extent -3.3,-3.3 3.3,3.3, height 2.69
Pb-Free_Overlay_Small [mil]
  silkscreen extent -46,-46 46,46
Phoenix_1707027 [mm] "Terminal Block, 7.62mm, 2 Pos, TH"
  rect 1.8x1.8 hole 1.3: 1(-3.81,0)
  round 1.8 hole 1.3: 2(3.81,0)
  silkscreen extent -8.19,-4.05 7.62,4.05, body extent -8.19,-4.05 7.62,4.05, height 10
PT-48 [mil]
  rect 11.81x60 smd mask+1.97: 1(-108.4,-165.9) 2(-88.7,-165.9) 3(-69,-165.9) 4(-49.3,-165.9) 5(-29.6,-165.9) 6(-9.9,-165.9) 7(9.8,-165.9) 8(29.5,-165.9) 9(49.2,-165.9) 10(68.9,-165.9) 11(88.6,-165.9) 12(108.3,-165.9) 25(108.3,166.1) 26(88.6,166.1) 27(68.9,166.1) 28(49.2,166.1) 29(29.5,166.1) 30(9.8,166.1) 31(-9.9,166.1) 32(-29.6,166.1) 33(-49.3,166.1) 34(-69,166.1) 35(-88.7,166.1) 36(-108.4,166.1)
  rect 60x11.81 smd mask+1.97: 13(166,-108.2) 14(166,-88.5) 15(166,-68.8) 16(166,-49.1) 17(166,-29.4) 18(166,-9.7) 19(166,10) 20(166,29.7) 21(166,49.4) 22(166,69.1) 23(166,88.8) 24(166,108.5) 37(-165.9,108.5) 38(-165.9,88.8) 39(-165.9,69.1) 40(-165.9,49.4) 41(-165.9,29.7) 42(-165.9,10) 43(-165.9,-9.7) 44(-165.9,-29.4) 45(-165.9,-49.1) 46(-165.9,-68.8) 47(-165.9,-88.5) 48(-165.9,-108.2)
  silkscreen extent -239,-233 -219,-213
RZ_500x900 [mm] "NICHICON"
  rect 1.25x1.25 hole 0.75: 1(-1,0)
  round 1.25 hole 0.75: 2(1,0)
  silkscreen extent -2.82,-2.82 2.82,2.81, body extent -2.73,-2.75 2.75,2.75, height 10.51
SMA [mm] "Molded Diode, 2-Leads, Body 4.3x2.6mm, IPC Medium Density, based on OnSemi component dimensions and land pattern"
  rect 2x2 smd: 1(-2,0) 2(2,0)
  silkscreen extent -3.66,-1.57 2.79,1.57, body extent -2.6,-1.3 2.6,1.3, height 2.42
sod-123 [mm]
  rect 0.915x1.22 smd: 1(-1.637,0) 2(1.637,0)
  silkscreen extent -2.74,-1.17 2.03,1.17, body extent -1.93,-0.9 1.93,0.9, height 1.35
SOD-123 [mm] "On Semi recommended land pattern"
  rect 0.915x1.22 smd: 1(-1.637,0) 2(1.637,0)
  silkscreen extent -2.74,-1.17 2.03,1.17, body extent -1.93,-0.9 1.93,0.9, height 1.35
SOD-723 [mm] "SMD, 2-Leads, Body 1x0.6mm"
  rect 0.6x0.7 smd: 1(-0.6,0) 2(0.6,0)
  silkscreen extent -1.5,-0.7 0.9,0.7, body extent -0.75,-0.33 0.75,0.33, height 0.65
SOT-23 [mm] "SOT23, 3-Leads, Body 2.9x1.3mm, Pitch 0.95mm, Lead Span 2.5mm, IPC Medium Density"
  rrect50% 1x0.6 smd: 1(-1.2,0.95) 2(-1.2,-0.95) 3(1.2,0)
  silkscreen extent -1.63,-1.5 0.7,1.5, body extent -1.16,-1.45 1.21,1.45, height 1
SW_434121025816 [mm] "SMD, 2-Leads, Body 6x3.9mm, Pitch 6.5mm"
  rect 1.5x1.4 smd: 1(-3.25,0) 2(3.25,0)
  silkscreen extent -3,-1.95 3,1.95, body extent -3.65,-1.95 3.65,1.95, height 2.5
TI_Horizontal_Overlay_Small [mil]
  silkscreen extent -545,-68 545,67
TO-220AB_HORIZONTAL [mm] "For SolarMagic, with tab facing heatsink, away from PCB"
  rrect5% 1.5x3 hole 1.2: 1(2.54,0)
  rrect100% 1.5x3 hole 1.2: 2(0,0) 3(-2.54,0)
  silkscreen extent -5.34,2 5.34,20.32, body extent -5.34,-0.3 5.34,20.33, height 4.88
tssop-14 [mm] "TSSOP, 14-Leads, Body 5x4.4mm, Pitch 0.65mm, IPC Low Density"
  oval 1.7x0.35 smd: 1(-2.85,1.95) 2(-2.85,1.3) 3(-2.85,0.65) 4(-2.85,0) 5(-2.85,-0.65) 6(-2.85,-1.3) 7(-2.85,-1.95) 8(2.85,-1.95) 9(2.85,-1.3) 10(2.85,-0.65) 11(2.85,0) 12(2.85,0.65) 13(2.85,1.3) 14(2.85,1.95)
  silkscreen extent -1.7,-2.55 1.7,2.55, body extent -3.21,-2.5 3.21,2.5, height 0.98
WL-SMCW_GREEN [mm] "WURTH"
  rect 0.8x0.8 smd: 1(-0.8,0) 2(0.8,0)
  silkscreen extent -1.9,-0.8 1.2,0.8, body extent -0.85,-0.45 0.85,0.45, height 0.8

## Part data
3 4: library part IEC_HotSurface, "IEC 61010-1 Hot Surface Warning"
5 6: library part IEC_HighVoltage, "IEC 61010-1 High Voltage Warning"
C1 C2 C4 C8 C12 C18 C39 C43 C44 C48 C49 C51 C52 C54 C56 C58: "CAP, CERM, 0.1 µF, 16 V, +/- 5%, X7R, 0603", Cap_Case=0603, Manufacturer=AVX, Supplier Part Number 1=478-3726-1-ND, TempCo=X7R, Tolerance_%=5, Value1="0.039 ohm", Value2=16V, ValueDisplayed=0.1µF
C5 C13 C19 C68: "CAP, CERM, 220 pF, 50 V, +/- 1%, C0G/NP0, 0603", Cap_Case=0603, Manufacturer=AVX, Supplier Part Number 1=478-3719-1-ND, TempCo=C0G/NP0, Tolerance_%=1, Value1="0.083 ohm", Value2=50V, ValueDisplayed=1000pF
C6 C14 C20: "CAP, CERM, 220 pF, 50 V, +/- 1%, C0G/NP0, 0603", Cap_Case=0603, Manufacturer=AVX, Supplier Part Number 1=478-3719-1-ND, TempCo=C0G/NP0, Tolerance_%=1, Value1="0.083 ohm", Value2=50V, ValueDisplayed=330pF
C7 C15 C21: "CAP, CERM, 220 pF, 50 V, +/- 1%, C0G/NP0, 0603", Cap_Case=0603, Manufacturer=AVX, Supplier Part Number 1=478-3719-1-ND, TempCo=C0G/NP0, Tolerance_%=1, Value1="0.083 ohm", Value2=50V, ValueDisplayed=3.3pF
C9 C42 C45: "CAP, CERM, 220 pF, 50 V, +/- 1%, C0G/NP0, 0603", Cap_Case=0603, Manufacturer=AVX, Supplier Part Number 1=478-3719-1-ND, TempCo=C0G/NP0, Tolerance_%=1, Value1="0.083 ohm", Value2=50V, ValueDisplayed=220pF
C10 C16 C22: library part C0603C220J5GACTU, "CAP, CERM, 22 pF, 50 V, +/- 5%, C0G/NP0, 0603", Cap_Case=0603, Manufacturer=Kemet, Supplier Part Number 1=399-1053-1-ND, TempCo=C0G/NP0, Tolerance_%=5, Value1=Unknown, Value2=50V, ValueDisplayed=3.3pF
C23 C32 C38: "CAP, CERM, 10 µF, 25 V, +/- 10%, X5R, 0805", Cap_Case=0805, Manufacturer=TDK, Supplier Part Number 1=445-5984-1-ND, TempCo=X5R, Tolerance_%=10, Value1=Unknown, Value2=25V, ValueDisplayed=10µF
C24 C25 C26: "CAP, CERM, 0.1 µF, 1000 V, +/- 10%, X7R, 1812", Cap_Case=1812, Manufacturer=Kemet, Supplier Part Number 1=399-6493-1-ND, TempCo=X7R, Tolerance_%=10, Value1=Unknown, Value2=1000V, ValueDisplayed=0.1µF
C27 C31 C33 C37 C40 C46: "CAP, CERM, 2200 pF, 25 V, +/- 10%, X7R, 0603", Cap_Case=0603, Manufacturer=MuRata, Supplier Part Number 1=GRM188R71E222KA01D-ND, TempCo=X7R, Tolerance_%=10, Value1=Unknown, Value2=25V, ValueDisplayed=2200pF
C28 C34 C41 C65 C66 C67: "CAP, CERM, 1 µF, 25 V, +/- 10%, X7R, 0805", Cap_Case=0805, Manufacturer=Kemet, Supplier Part Number 1=399-8004-1-ND, TempCo=X7R, Tolerance_%=10, Value1=Unknown, Value2=25V, ValueDisplayed=680nF
C29 C30 C35 C36: "CAP, CERM, 220 pF, 50 V, +/- 1%, C0G/NP0, 0603", Cap_Case=0603, Manufacturer=AVX, Supplier Part Number 1=478-3719-1-ND, TempCo=C0G/NP0, Tolerance_%=1, Value1="0.083 ohm", Value2=50V, ValueDisplayed=33pF
C47 C53 C55 C57: "CAP, CERM, 4.7 µF, 16 V, +/- 10%, X7R, 0805", Cap_Case=0805, Manufacturer=MuRata, Supplier Part Number 1=490-4522-1-ND, TempCo=X7R, Tolerance_%=10, Value1="0.006 ohm", Value2=16V, ValueDisplayed=4.7µF
C50: "CAP, AL, 68 µF, 450 V, +/- 20%, TH", Cap_Case=18x31.5mm, Manufacturer=Nichicon, Supplier Part Number 1=493-13090-ND, Tolerance_%=20, Value1=Unknown, Value2=450V, ValueDisplayed=68µF
C59: "CAP, AL, 22 µF, 25 V, +/- 20%, TH", Cap_Case=5x9mm, Manufacturer=Nichicon, Supplier Part Number 1=493-11557-1-ND, Tolerance_%=20, Value1=Unknown, Value2=25V, ValueDisplayed=22µF
C60: "CAP, CERM, 0.1 µF, 25 V, +/- 10%, X7R, 0603", Cap_Case=0603, Manufacturer=AVX, Supplier Part Number 1=478-3714-1-ND, TempCo=X7R, Tolerance_%=10, Value1="0.05 ohm", Value2=25V, ValueDisplayed=0.1µF
C61 C62 C63 C64: "CAP, CERM, 0.047 µF, 25 V, +/- 5%, X7R, 0603", Cap_Case=0603, Manufacturer=AVX, Supplier Part Number 1=478-3716-1-ND, TempCo=X7R, Tolerance_%=5, Value1="0.052 ohm", Value2=25V, ValueDisplayed=0.047µF
Caution: library part IEC_Caution, "IEC 61010-1 Caution Warning"
D1 D3 D4 D5: library part 1N5363BRLG, "Diode, Zener, 30 V, 5 W, Axial Diode", Manufacturer="ON Semiconductor", Power_W=5, Supplier Part Number 1=1N5363BRLGOSCT-ND, Value1=5W
D2 D6 D7 D8: "Diode, Zener, 30 V, 5 W, Axial Diode", Manufacturer="ON Semiconductor", Power_W=5, Supplier Part Number 1=1N5363BRLGOSCT-ND, Value1=5W
D9 D12 D15: "Diode, Ultrafast, 1000V, 1A, SMA", Manufacturer="Diodes Inc.", Supplier Part Number 1=US1M-FDICT-ND, Value1=1A, Value2=1.7V
D10 D11 D13 D14 D16 D17 D21: "Diode, Schottky, 40V, 1A, SOD-123", Manufacturer="Diodes Inc.", Supplier Part Number 1=1N5819HW-FDICT-ND, Value1=1A, Value2=0.45V
D18: "LED, Green, SMD", Color=Green, Manufacturer="Wurth Elektronics Inc", Supplier Part Number 1=732-4971-1-ND, Value1=W, Value2=3.2V
D19: "LED YELLOW CLEAR 0603 SMD", Color=Yellow, Manufacturer="Wurth Elektronics Inc", PartNumber=150060YS75000, Supplier Part Number 1=732-4981-1-ND, Value1=W, Value2=2V
D20: "LED RED CLEAR 0603 SMD", Color=Red, Manufacturer="Wurth Elektronics Inc", PartNumber=150060RS75000, Supplier Part Number 1=732-4978-1-ND, Value1=W, Value2=2V
D22 D23 D24 D25: "Diode, Schottky, 30 V, 0.1 A, SOD-723", Manufacturer="Comchip Technology", Supplier Part Number 1=641-1135-1-ND, Value1=0.1A, Value2=0.35V
FID1 FID2 FID3 FID4 FID5 FID6: "Fiducial mark.  There is nothing to buy or mount.", Manufacturer=N/A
